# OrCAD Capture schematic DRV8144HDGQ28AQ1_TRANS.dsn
size Custom; title: DRV8144-Q1 Automotive Half Bridge Driver with; rev: 1.0; note: Datasheet: SLVSG25      EVM: NA; note: Synchronous Step Down Converter
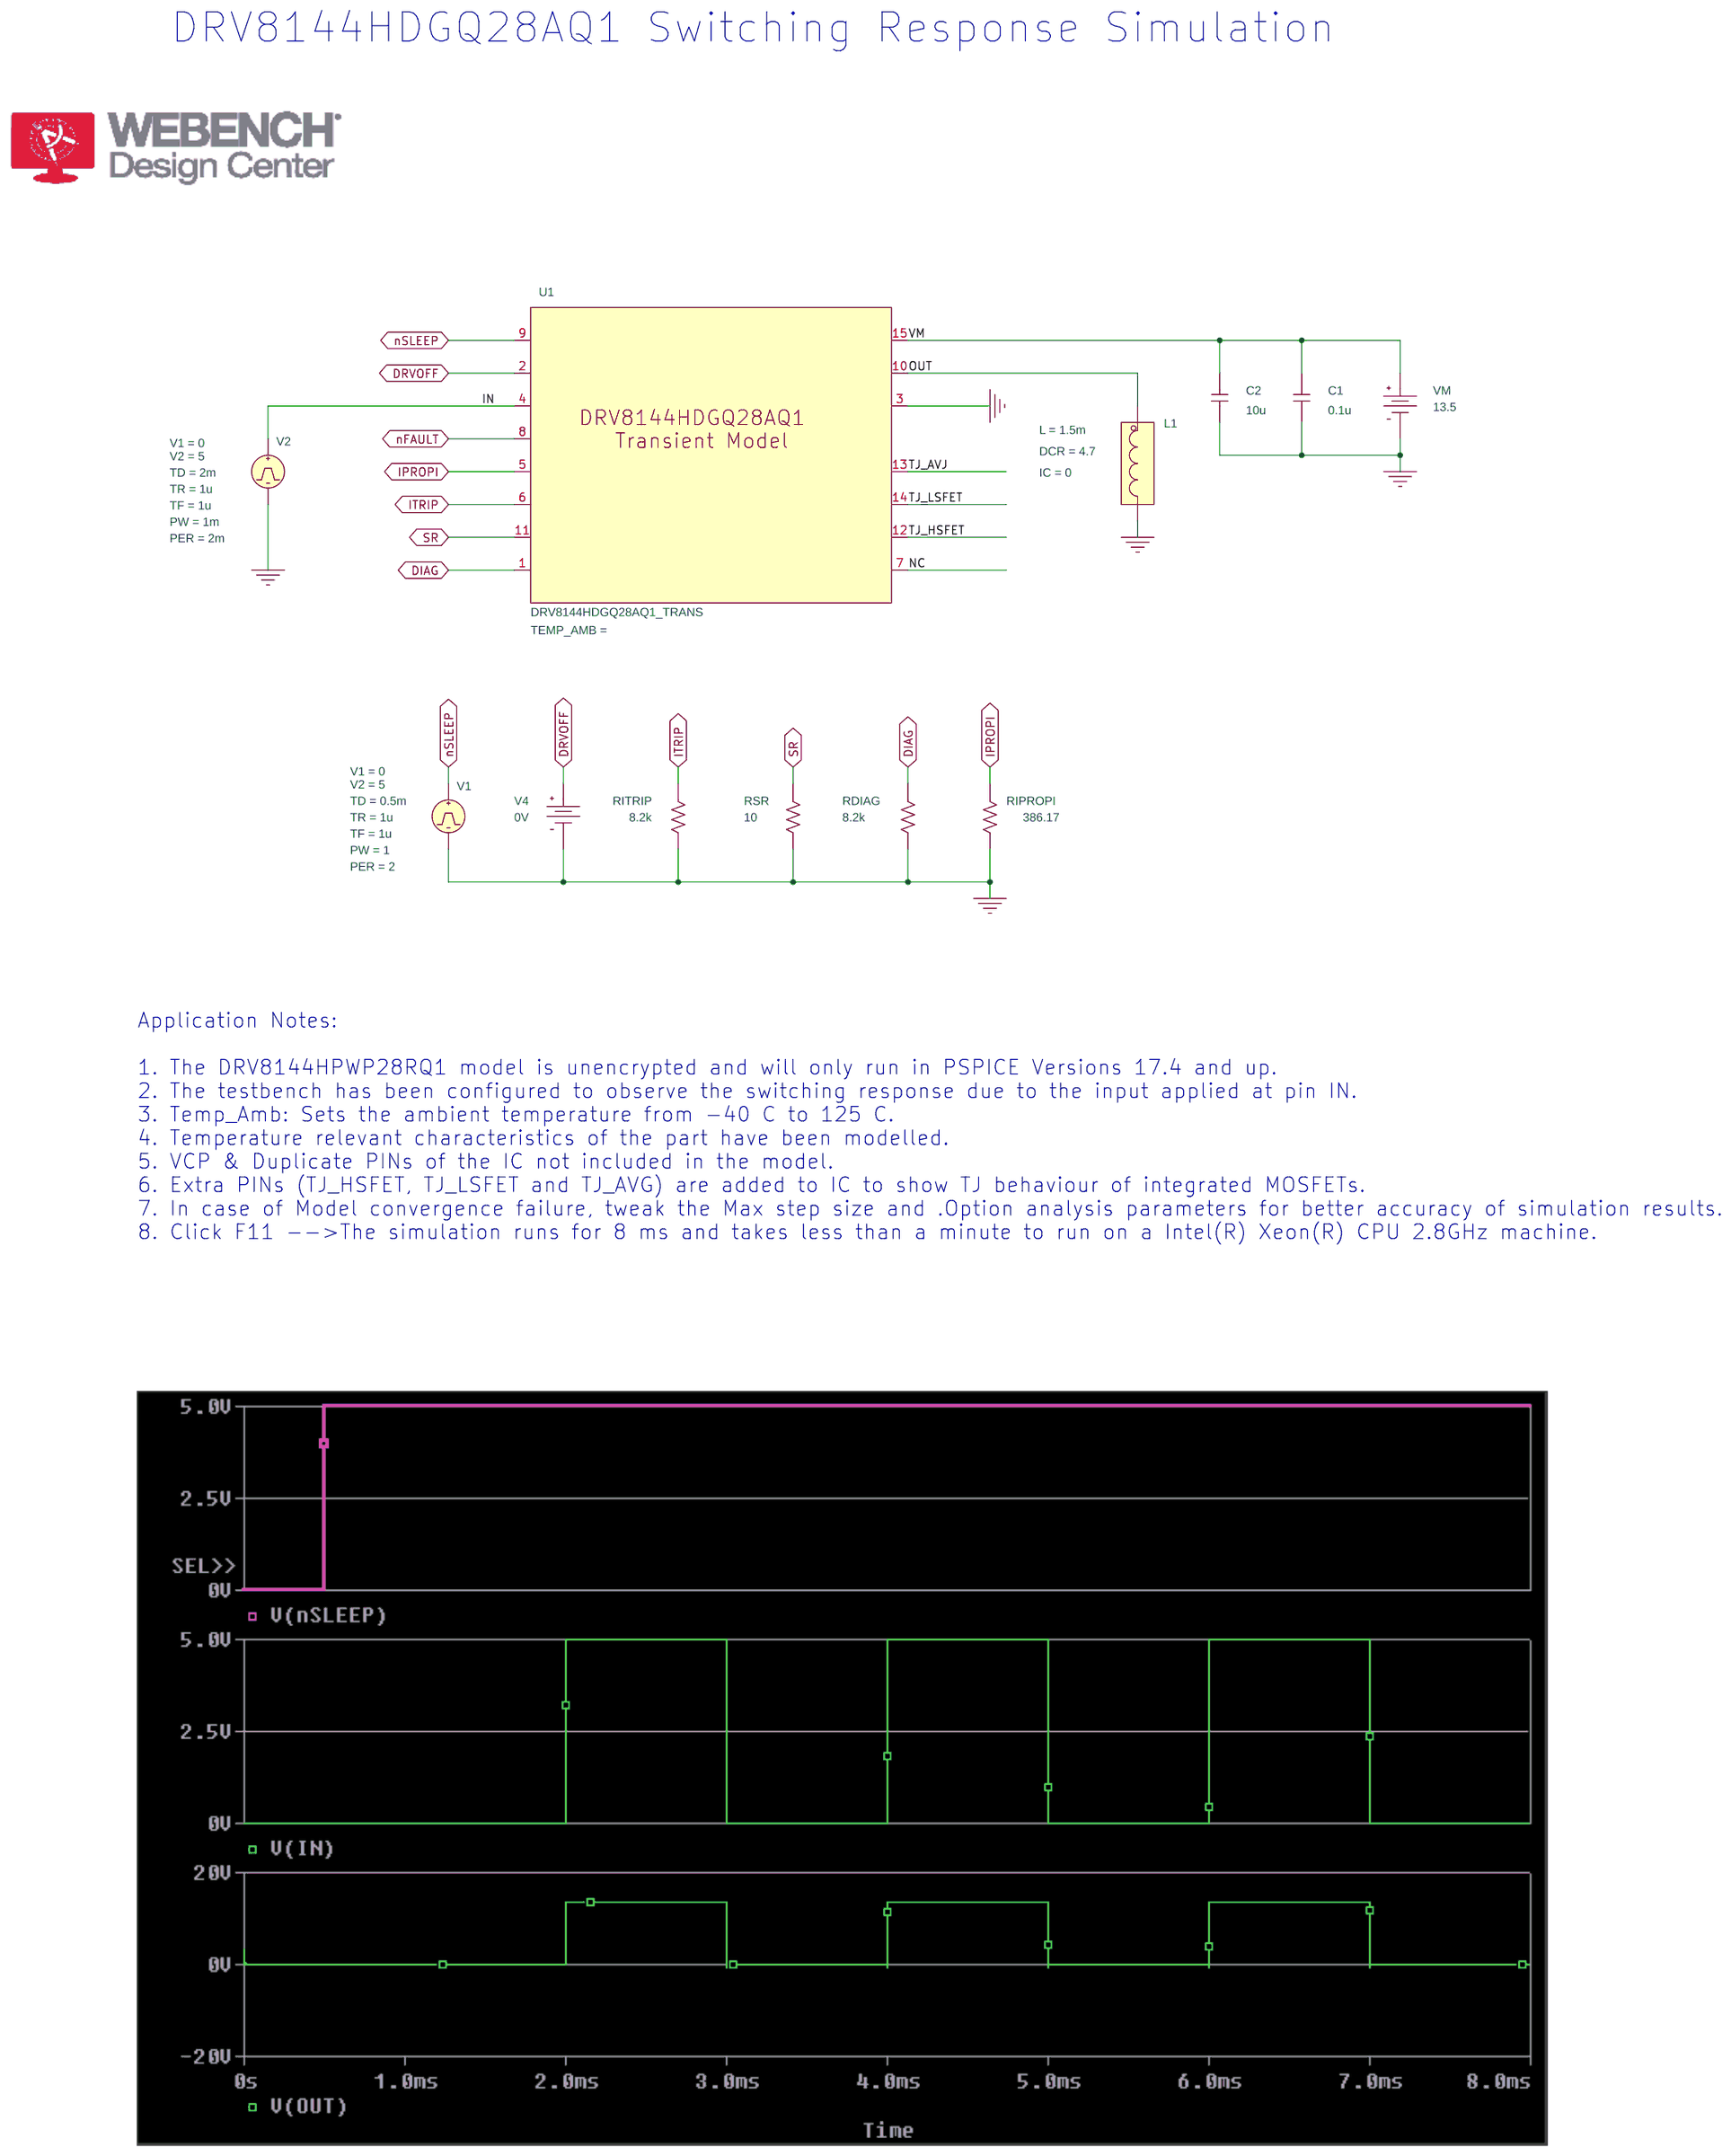
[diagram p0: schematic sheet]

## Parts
C1  0.1u  [RAD/CK05]
C2  10u  [RAD/CK05]
L1  LDCR
RDIAG  8.2k  [AXRC05]
RIPROPI  386.17  [AXRC05]
RITRIP  8.2k  [AXRC05]
RSR  10  [AXRC05]
U1  DRV8144HDGQ28AQ1_TRANS
V1  VPULSE
V2  VPULSE
V4  VDC
VM  VDC

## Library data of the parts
C1 C2 = C
L1 = LDCR: DCR: 4.7; IC: 0; L: 1.5m; PSpiceTemplate: X^@REFDES %IN %OUT @MODEL PARAMS:  ?L|L=@L||L=1u|  ?DCR|DCR=@DCR||DCR=0.01| ?IC|IC=@IC||IC=0|
RDIAG RIPROPI RITRIP RSR = R
U1 = DRV8144HDGQ28AQ1_TRANS
V1 = VPULSE: PER: 2; PW: 1; TD: 0.5m; TF: 1u; TR: 1u; V1: 0; V2: 5
V2 = VPULSE: PER: 2m; PW: 1m; TD: 2m; TF: 1u; TR: 1u; V1: 0; V2: 5
V4 = VDC: DC: 0V
VM = VDC: DC: 13.5

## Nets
0: C1.2 C2.2 L1.3(OUT) RDIAG.2 RIPROPI.2 RITRIP.2 RSR.2 U1.3(GND) V1.2(-) V2.2(-) V4.1(-) VM.1(-)
DIAG: RDIAG.1 U1.1(DIAG)
DRVOFF: U1.2(DRVOFF) V4.0(+)
IN: U1.4(IN) V2.1(+)
IPROPI: RIPROPI.1 U1.5(IPROPI)
ITRIP: RITRIP.1 U1.6(ITRIP)
NC: U1.7(NC)
nFAULT: U1.8(nFAULT)
nSLEEP: U1.9(nSLEEP) V1.1(+)
OUT: L1.1(IN) U1.10(OUT)
SR: RSR.1 U1.11(SR)
TJ_AVJ: U1.13(TJ_HSFET)
TJ_HSFET: U1.12(TJ_AVG)
TJ_LSFET: U1.14(TJ_LSFET)
VM: C1.1 C2.1 U1.15(VM) VM.0(+)

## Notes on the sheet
- DRV8144HDGQ28AQ1 Switching Response Simulation
- Application Notes:
  1. The DRV8144HPWP28RQ1 model is unencrypted and will only run in PSPICE Versions 17.4 and up.
  2. The testbench has been configured to observe the switching response due to the input applied at pin IN.
  3. Temp_Amb: Sets the ambient temperature from -40 C to 125 C.
  4. Temperature relevant characteristics of the part have been modelled.
  5. VCP & Duplicate PINs of the IC not included in the model.
  6. Extra PINs (TJ_HSFET, TJ_LSFET and TJ_AVG) are added to IC to show TJ behaviour of integrated MOSFETs.
  7. In case of Model convergence failure, tweak the Max step size and .Option analysis parameters for better accuracy of simulation results.
  8. Click F11 -->The simulation runs for 8 ms and takes less than a minute to run on a Intel(R) Xeon(R) CPU 2.8GHz machine.
